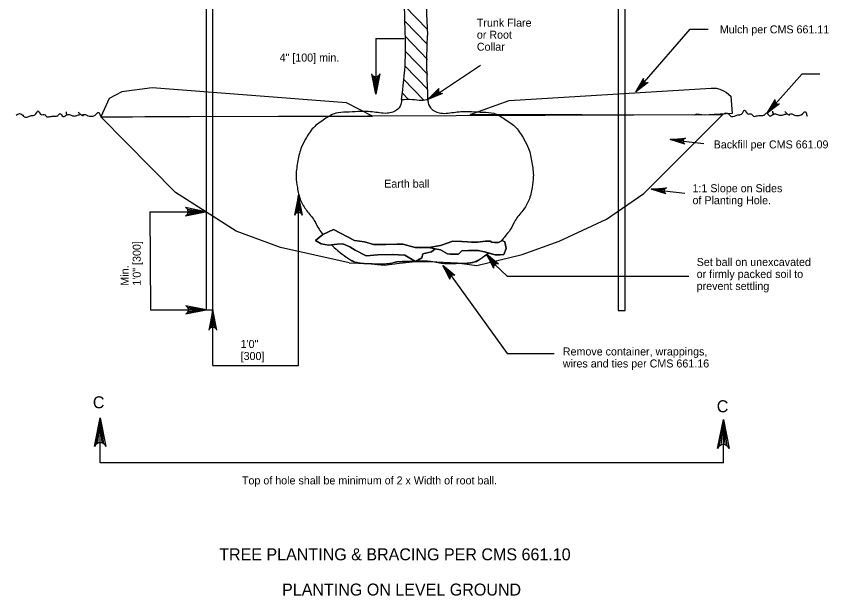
# Model space of a CAD drawing. Extents: x 3862.5 to 3891, y 3400.3 to 3419.7.
# Drawn here: x 3862.53 to 3876.75, y 3401.3 to 3411.44 of the extents above; entities that cross this region are included whole.
import ezdxf

# ---------------------------------------------------------------- set-up
doc = ezdxf.new("R2010")
doc.units = 0
doc.layers.add('DR_X_Trench_Drain', color=7, linetype='Continuous')
doc.layers.add('GT_X_Coal_Seam_1', color=7, linetype='Continuous')

msp = doc.modelspace()

# ---------------------------------------------------------------- linework, layer by layer
at = {"layer": 'DR_X_Trench_Drain'}
for p, q in [((3869.328, 3411.618), (3869.727, 3411.206)), ((3869.331, 3411.355), (3869.726, 3410.947)), ((3869.333, 3411.092), (3869.728, 3410.684)), ((3869.335, 3410.829), (3869.73, 3410.421)), ((3869.329, 3410.575), (3869.733, 3410.158)), ((3869.305, 3410.339), (3869.656, 3409.977)), ((3869.282, 3410.102), (3869.395, 3409.985)), ((3864.009, 3409.68), (3874.891, 3409.72)), ((3874.891, 3409.72), (3873.513, 3408.341)), ((3865.317, 3408.359), (3864.009, 3409.68))]:
    msp.add_line(p, q, dxfattribs=at)
for points in [[(3865.968, 3415.198), (3865.968, 3415.572), (3865.853, 3415.572), (3865.853, 3406.305), (3865.968, 3406.305), (3865.968, 3415.064)], [(3873.059, 3414.731), (3873.059, 3406.291), (3873.183, 3406.291), (3873.183, 3415.584), (3873.059, 3415.584), (3873.059, 3414.859)], [(3868.357, 3407.125), (3867.154, 3407.393), (3866.377, 3407.681), (3865.317, 3408.359)], [(3870.586, 3407.078), (3871.383, 3407.271), (3872.027, 3407.504), (3872.859, 3407.892), (3873.513, 3408.341)], [(3868.047, 3407.443), (3868.142, 3407.454), (3868.242, 3407.459), (3868.364, 3407.409), (3868.458, 3407.348), (3868.653, 3407.248), (3868.858, 3407.265), (3869.108, 3407.271), (3869.33, 3407.259), (3869.514, 3407.153), (3869.624, 3407.215), (3869.646, 3407.282), (3869.796, 3407.32), (3869.862, 3407.37), (3869.751, 3407.398), (3869.507, 3407.393), (3869.296, 3407.454), (3869.191, 3407.454), (3868.997, 3407.448), (3868.78, 3407.448), (3868.625, 3407.493), (3868.447, 3407.52), (3868.081, 3407.709), (3867.897, 3407.622), (3867.892, 3407.62), (3867.765, 3407.515), (3867.865, 3407.459), (3867.992, 3407.437), (3868.047, 3407.443)], [(3869.514, 3407.153), (3869.33, 3407.259), (3869.108, 3407.271), (3868.858, 3407.265), (3868.653, 3407.248), (3868.458, 3407.348), (3868.364, 3407.409), (3868.242, 3407.459), (3868.142, 3407.454), (3868.047, 3407.443)], [(3869.751, 3407.398), (3869.951, 3407.431), (3870.168, 3407.504), (3870.168, 3407.504), (3870.329, 3407.498), (3870.423, 3407.493), (3870.495, 3407.487), (3870.601, 3407.487), (3870.739, 3407.504), (3870.823, 3407.504), (3870.85, 3407.487), (3870.9, 3407.481), (3870.967, 3407.481), (3871.033, 3407.52), (3871.078, 3407.493), (3871.1, 3407.376), (3871.061, 3407.271), (3870.995, 3407.265), (3870.911, 3407.265), (3870.723, 3407.32), (3870.612, 3407.343), (3870.445, 3407.343), (3870.329, 3407.337), (3870.268, 3407.276), (3870.123, 3407.276), (3870.073, 3407.282), (3869.951, 3407.354), (3869.862, 3407.37)], [(3870.796, 3407.299), (3870.911, 3407.265), (3870.995, 3407.265), (3871.061, 3407.271), (3871.1, 3407.376), (3871.078, 3407.493), (3871.033, 3407.52), (3871.015, 3407.509), (3870.967, 3407.481), (3870.9, 3407.481), (3870.85, 3407.487), (3870.823, 3407.504), (3870.739, 3407.504), (3870.601, 3407.487), (3870.495, 3407.487), (3870.423, 3407.493), (3870.329, 3407.498), (3870.168, 3407.504), (3869.951, 3407.431), (3869.751, 3407.398), (3869.862, 3407.37), (3869.951, 3407.354), (3870.073, 3407.282), (3870.123, 3407.276), (3870.268, 3407.276), (3870.329, 3407.337), (3870.445, 3407.343), (3870.612, 3407.343), (3870.723, 3407.32), (3870.796, 3407.299)], [(3870.796, 3407.299), (3870.723, 3407.32), (3870.612, 3407.343), (3870.445, 3407.343), (3870.329, 3407.337), (3870.268, 3407.276), (3870.123, 3407.276), (3870.073, 3407.282), (3869.951, 3407.354), (3869.862, 3407.37), (3869.796, 3407.32), (3869.646, 3407.282), (3869.624, 3407.215), (3869.514, 3407.153)], [(3868.357, 3407.125), (3868.681, 3407.117), (3868.968, 3407.086), (3869.235, 3407.123), (3869.514, 3407.153), (3869.765, 3407.153), (3870.249, 3407.129), (3870.584, 3407.078), (3870.584, 3407.078), (3870.586, 3407.078)], [(3869.748, 3407.153), (3869.765, 3407.153), (3870.249, 3407.129), (3870.332, 3407.116)], [(3870.691, 3407.223), (3870.689, 3407.226), (3870.692, 3407.224)], [(3868.62, 3407.119), (3868.681, 3407.117), (3868.701, 3407.115)]]:
    msp.add_lwpolyline(points, dxfattribs=at)
for points in [[(3864.375, 3410.118), (3864.375, 3410.118), (3864.375, 3410.118), (3864.157, 3410.001), (3864.009, 3409.68), (3864.564, 3409.681), (3864.779, 3409.686), (3868.764, 3409.695), (3868.311, 3409.924), (3864.907, 3410.187)], [(3874.776, 3410.182), (3874.842, 3410.167), (3874.904, 3410.136), (3874.954, 3410.105), (3875.031, 3410.044), (3875.055, 3409.737), (3874.742, 3409.724), (3874.566, 3409.71), (3874.439, 3409.73), (3874.394, 3409.71), (3870.474, 3409.72), (3871.157, 3409.967), (3874.691, 3410.184)], [(3867.892, 3407.62), (3868.081, 3407.709), (3868.447, 3407.52), (3868.625, 3407.493), (3868.78, 3407.448), (3868.997, 3407.448), (3869.191, 3407.454), (3869.296, 3407.454), (3869.507, 3407.393), (3869.751, 3407.398), (3869.862, 3407.37), (3869.796, 3407.32), (3869.646, 3407.282), (3869.624, 3407.215), (3869.514, 3407.153), (3869.33, 3407.259), (3869.108, 3407.271), (3868.858, 3407.265), (3868.653, 3407.248), (3868.458, 3407.348), (3868.364, 3407.409), (3868.242, 3407.459), (3868.142, 3407.454), (3867.992, 3407.437), (3867.865, 3407.459), (3867.765, 3407.515)]]:
    msp.add_lwpolyline(points, close=True, dxfattribs=at)
for points in [[(3869.27, 3409.985), (3869.337, 3410.657), (3869.331, 3411.318), (3869.325, 3411.994), (3869.342, 3412.725), (3869.348, 3413.532), (3869.366, 3414.555), (3869.391, 3415.303), (3869.383, 3415.572)], [(3869.729, 3411.112), (3869.703, 3412.101), (3869.725, 3413.333), (3869.747, 3414.452), (3869.747, 3415.124), (3869.791, 3415.482)], [(3869.734, 3409.985), (3869.725, 3411.048), (3869.729, 3411.112)], [(3869.27, 3409.985), (3869.267, 3409.924), (3869.205, 3409.815), (3869.018, 3409.742), (3868.758, 3409.768), (3868.508, 3409.772), (3868.304, 3409.763), (3868.12, 3409.743), (3867.926, 3409.641), (3867.73, 3409.491), (3867.592, 3409.29), (3867.512, 3409.127), (3867.451, 3408.881), (3867.427, 3408.629), (3867.448, 3408.446), (3867.506, 3408.221), (3867.611, 3408.043), (3867.743, 3407.868), (3867.828, 3407.714), (3867.897, 3407.622)], [(3869.27, 3409.985), (3869.456, 3409.985), (3869.624, 3409.973), (3869.734, 3409.985)], [(3869.734, 3409.985), (3869.737, 3409.924), (3869.799, 3409.815), (3869.987, 3409.742), (3870.247, 3409.768), (3870.496, 3409.772), (3870.7, 3409.763), (3870.885, 3409.743), (3871.078, 3409.641), (3871.275, 3409.491), (3871.412, 3409.29), (3871.493, 3409.127), (3871.553, 3408.881), (3871.577, 3408.629), (3871.556, 3408.446), (3871.499, 3408.221), (3871.393, 3408.043), (3871.261, 3407.868), (3871.177, 3407.714), (3871.07, 3407.576), (3871.015, 3407.509)], [(3862.53, 3409.708), (3862.589, 3409.738), (3862.628, 3409.722), (3862.686, 3409.674), (3862.733, 3409.681), (3862.793, 3409.702), (3862.858, 3409.716), (3862.91, 3409.787), (3862.978, 3409.716), (3863.021, 3409.724), (3863.067, 3409.683), (3863.138, 3409.689), (3863.183, 3409.694), (3863.212, 3409.693), (3863.245, 3409.696), (3863.266, 3409.708), (3863.295, 3409.739), (3863.349, 3409.687), (3863.389, 3409.698), (3863.455, 3409.724), (3863.49, 3409.707), (3863.543, 3409.695), (3863.602, 3409.709), (3863.661, 3409.727)], [(3863.402, 3409.77), (3863.402, 3409.744), (3863.424, 3409.71)], [(3863.616, 3409.763), (3863.655, 3409.725), (3863.699, 3409.698)], [(3863.691, 3409.719), (3863.74, 3409.722), (3863.785, 3409.698), (3863.835, 3409.69), (3863.903, 3409.706), (3863.974, 3409.755), (3863.998, 3409.711), (3864.009, 3409.68)], [(3874.891, 3409.72), (3874.95, 3409.749), (3874.99, 3409.734), (3875.047, 3409.685), (3875.094, 3409.693), (3875.154, 3409.713), (3875.219, 3409.727), (3875.271, 3409.798), (3875.339, 3409.728), (3875.383, 3409.735), (3875.428, 3409.694), (3875.499, 3409.701), (3875.544, 3409.705), (3875.573, 3409.704), (3875.606, 3409.707), (3875.628, 3409.719), (3875.656, 3409.75), (3875.711, 3409.698), (3875.75, 3409.709), (3875.817, 3409.736), (3875.851, 3409.719), (3875.904, 3409.707), (3875.963, 3409.721), (3876.022, 3409.738)], [(3875.764, 3409.781), (3875.764, 3409.755), (3875.785, 3409.722)], [(3875.977, 3409.775), (3876.016, 3409.736), (3876.06, 3409.709)], [(3876.052, 3409.73), (3876.101, 3409.734), (3876.146, 3409.709), (3876.196, 3409.702), (3876.264, 3409.717), (3876.335, 3409.767), (3876.359, 3409.722), (3876.37, 3409.692)], [(3868.047, 3407.443), (3868.062, 3407.427), (3868.193, 3407.311), (3868.348, 3407.199), (3868.467, 3407.14), (3868.701, 3407.115), (3869.013, 3407.113), (3869.247, 3407.152), (3869.514, 3407.153)], [(3870.796, 3407.299), (3870.657, 3407.199), (3870.537, 3407.14), (3870.303, 3407.115), (3869.992, 3407.113), (3869.757, 3407.152), (3869.514, 3407.153)]]:
    msp.add_spline(points, degree=3, dxfattribs=at)
for points, degree in [([(3868.047, 3407.443), (3868.052, 3407.438), (3868.057, 3407.433), (3868.062, 3407.427), (3868.102, 3407.384), (3868.148, 3407.348), (3868.193, 3407.311), (3868.243, 3407.271), (3868.294, 3407.235), (3868.348, 3407.199), (3868.385, 3407.175), (3868.423, 3407.151), (3868.467, 3407.14), (3868.518, 3407.127), (3868.569, 3407.122), (3868.62, 3407.119)], 3), ([(3870.692, 3407.224), (3870.728, 3407.248), (3870.762, 3407.273), (3870.796, 3407.299)], 2), ([(3868.701, 3407.115), (3868.701, 3407.115), (3868.701, 3407.115), (3868.701, 3407.115), (3868.805, 3407.111), (3868.91, 3407.107), (3869.013, 3407.113), (3869.092, 3407.118), (3869.168, 3407.152), (3869.247, 3407.152), (3869.336, 3407.153), (3869.425, 3407.153), (3869.514, 3407.153)], 3), ([(3869.514, 3407.153), (3869.592, 3407.158), (3869.671, 3407.158), (3869.748, 3407.153)], 2), ([(3870.332, 3407.116), (3870.401, 3407.119), (3870.469, 3407.123), (3870.537, 3407.14), (3870.581, 3407.151), (3870.62, 3407.174), (3870.657, 3407.199), (3870.668, 3407.207), (3870.68, 3407.215), (3870.691, 3407.223)], 3)]:
    msp.add_open_spline(points, degree=degree, dxfattribs=at)
at = {"layer": 'GT_X_Coal_Seam_1'}
for p, q in [((3873.521, 3410.29), (3874.324, 3411.213)), ((3874.324, 3411.213), (3874.636, 3411.213)), ((3868.819, 3411.051), (3868.819, 3410.077)), ((3868.819, 3411.051), (3869.319, 3411.051)), ((3869.919, 3410.096), (3870.653, 3410.586)), ((3868.775, 3410.397), (3868.819, 3410.077)), ((3868.869, 3410.401), (3868.819, 3410.077)), ((3875.671, 3409.745), (3876.279, 3410.434)), ((3876.279, 3410.434), (3876.591, 3410.434)), ((3868.797, 3410.386), (3868.819, 3410.077)), ((3868.848, 3410.389), (3868.819, 3410.077)), ((3868.819, 3410.383), (3868.819, 3410.077)), ((3873.503, 3410.32), (3873.369, 3410.117)), ((3873.51, 3410.303), (3873.369, 3410.117)), ((3873.521, 3410.29), (3873.369, 3410.117)), ((3873.54, 3410.279), (3873.369, 3410.117)), ((3873.558, 3410.275), (3873.369, 3410.117)), ((3869.916, 3410.147), (3869.734, 3409.985)), ((3869.918, 3410.129), (3869.734, 3409.985)), ((3869.926, 3410.113), (3869.734, 3409.985)), ((3869.941, 3410.097), (3869.734, 3409.985)), ((3869.958, 3410.089), (3869.734, 3409.985)), ((3875.805, 3409.948), (3875.671, 3409.745)), ((3875.812, 3409.931), (3875.671, 3409.745)), ((3875.823, 3409.918), (3875.671, 3409.745)), ((3875.842, 3409.907), (3875.671, 3409.745)), ((3875.86, 3409.903), (3875.671, 3409.745)), ((3874.213, 3409.292), (3873.97, 3409.285)), ((3874.198, 3409.259), (3873.97, 3409.285)), ((3874.2, 3409.237), (3873.97, 3409.285)), ((3874.208, 3409.221), (3873.97, 3409.285)), ((3874.203, 3409.276), (3873.97, 3409.285)), ((3874.207, 3409.254), (3874.56, 3409.212)), ((3873.88, 3408.423), (3873.637, 3408.416)), ((3873.866, 3408.391), (3873.637, 3408.416)), ((3873.868, 3408.369), (3873.637, 3408.416)), ((3873.875, 3408.352), (3873.637, 3408.416)), ((3873.87, 3408.407), (3873.637, 3408.416)), ((3867.423, 3407.992), (3867.468, 3408.313)), ((3867.445, 3408.003), (3867.468, 3408.313)), ((3867.468, 3408.006), (3867.468, 3408.313)), ((3867.497, 3408.001), (3867.468, 3408.313)), ((3867.518, 3407.988), (3867.468, 3408.313)), ((3873.875, 3408.385), (3874.227, 3408.343)), ((3864.87, 3408.022), (3865.844, 3408.022)), ((3864.87, 3408.022), (3864.879, 3406.305)), ((3865.52, 3407.972), (3865.844, 3408.022)), ((3865.524, 3408.067), (3865.844, 3408.022)), ((3865.532, 3407.993), (3865.844, 3408.022)), ((3865.534, 3408.044), (3865.844, 3408.022)), ((3865.538, 3408.022), (3865.844, 3408.022)), ((3867.468, 3405.33), (3867.468, 3408.006)), ((3870.901, 3407.097), (3870.758, 3407.277)), ((3870.921, 3407.107), (3870.758, 3407.277)), ((3870.939, 3407.109), (3870.758, 3407.277)), ((3870.889, 3407.084), (3870.758, 3407.277)), ((3870.881, 3407.067), (3870.758, 3407.277)), ((3870.139, 3406.901), (3869.996, 3407.082)), ((3870.158, 3406.911), (3869.996, 3407.082)), ((3870.176, 3406.914), (3869.996, 3407.082)), ((3870.127, 3406.889), (3869.996, 3407.082)), ((3870.119, 3406.872), (3869.996, 3407.082)), ((3871.117, 3406.894), (3870.901, 3407.097)), ((3870.139, 3406.901), (3871.117, 3405.539)), ((3871.117, 3406.894), (3874.296, 3406.894)), ((3864.879, 3406.305), (3865.853, 3406.305)), ((3865.528, 3406.255), (3865.853, 3406.305)), ((3865.532, 3406.349), (3865.853, 3406.305)), ((3865.541, 3406.276), (3865.853, 3406.305)), ((3865.543, 3406.327), (3865.853, 3406.305)), ((3865.546, 3406.305), (3865.853, 3406.305)), ((3865.923, 3405.984), (3865.968, 3406.305)), ((3865.945, 3405.995), (3865.968, 3406.305)), ((3865.968, 3405.33), (3865.968, 3406.305)), ((3865.968, 3405.998), (3865.968, 3406.305)), ((3865.997, 3405.992), (3865.968, 3406.305)), ((3866.018, 3405.98), (3865.968, 3406.305)), ((3871.117, 3405.539), (3871.94, 3405.539)), ((3865.968, 3405.33), (3867.468, 3405.33)), ((3863.929, 3403.956), (3863.999, 3404.418)), ((3863.958, 3403.973), (3863.999, 3404.418)), ((3863.999, 3403.632), (3863.999, 3404.418)), ((3863.999, 3403.982), (3863.999, 3404.418)), ((3864.032, 3403.977), (3863.999, 3404.418)), ((3864.063, 3403.961), (3863.999, 3404.418)), ((3863.999, 3403.632), (3863.999, 3404.327)), ((3874.831, 3403.922), (3874.902, 3404.385)), ((3874.861, 3403.94), (3874.902, 3404.385)), ((3874.902, 3403.632), (3874.902, 3404.385)), ((3874.902, 3403.948), (3874.902, 3404.385)), ((3874.934, 3403.943), (3874.902, 3404.385)), ((3874.966, 3403.928), (3874.902, 3404.385)), ((3874.902, 3403.632), (3863.999, 3403.632))]:
    msp.add_line(p, q, dxfattribs=at)
for points in [[(3868.89, 3410.431), (3868.819, 3410.077), (3868.749, 3410.431)], [(3873.585, 3410.281), (3873.369, 3410.117), (3873.505, 3410.352)], [(3869.985, 3410.089), (3869.734, 3409.985), (3869.926, 3410.177)], [(3875.887, 3409.91), (3875.671, 3409.745), (3875.807, 3409.98)], [(3874.228, 3409.203), (3873.97, 3409.285), (3874.24, 3409.308)], [(3873.896, 3408.334), (3873.637, 3408.416), (3873.908, 3408.44)], [(3867.539, 3407.959), (3867.468, 3408.313), (3867.397, 3407.959)], [(3865.49, 3407.951), (3865.844, 3408.022), (3865.49, 3408.093)], [(3870.965, 3407.102), (3870.758, 3407.277), (3870.882, 3407.036)], [(3870.203, 3406.906), (3869.996, 3407.082), (3870.119, 3406.84)], [(3865.499, 3406.234), (3865.853, 3406.305), (3865.499, 3406.375)], [(3866.039, 3405.95), (3865.968, 3406.305), (3865.897, 3405.95)], [(3863.898, 3403.913), (3863.999, 3404.418), (3864.1, 3403.913)], [(3874.801, 3403.88), (3874.902, 3404.385), (3875.003, 3403.88)]]:
    msp.add_lwpolyline(points, dxfattribs=at)
for centre, radius, start, end in [((3868.819, 3410.459), 0.0764, 202.0878, 337.9139), ((3873.559, 3410.333), 0.0574, 160.6589, 296.485), ((3869.973, 3410.145), 0.0574, 145.7478, 281.574), ((3875.861, 3409.961), 0.0574, 160.6589, 296.485), ((3874.255, 3409.253), 0.0574, 105.7478, 241.574), ((3873.923, 3408.384), 0.0574, 105.7478, 241.574), ((3865.461, 3408.022), 0.0764, 292.0861, 67.9122), ((3867.468, 3407.93), 0.0764, 22.0861, 157.9122), ((3870.937, 3407.052), 0.0574, 60.4695, 196.2956), ((3870.174, 3406.856), 0.0574, 60.4695, 196.2956), ((3865.47, 3406.305), 0.0764, 292.0861, 67.9122), ((3865.968, 3405.922), 0.0764, 22.0861, 157.9122), ((3864, 3403.873), 0.109, 22.0878, 157.9139), ((3874.902, 3403.839), 0.109, 22.0878, 157.9139)]:
    msp.add_arc(centre, radius, start, end, dxfattribs=at)

# ---------------------------------------------------------------- texts
for s, height, p in [('Trunk Flare', 0.14, (3870.589, 3411.257)), ('Mulch per CMS 661.11', 0.14, (3874.84, 3411.14)), ('or Root', 0.14, (3870.589, 3411.047)), ('Collar', 0.14, (3870.589, 3410.837)), ('4" [100] min.', 0.14, (3867.138, 3410.647)), ('Backfill per CMS 661.09', 0.14, (3874.732, 3409.128)), ('Earth ball', 0.14, (3868.968, 3408.442)), ('1:1 Slope on Sides', 0.14, (3874.362, 3408.362)), ('of Planting Hole.', 0.14, (3874.362, 3408.152)), ('Set ball on unexcavated', 0.14, (3874.435, 3407.072)), ('or firmly packed soil to', 0.14, (3874.435, 3406.862)), ('prevent settling', 0.14, (3874.435, 3406.652)), ('1\'0"', 0.14, (3866.456, 3405.638)), ('[300]', 0.14, (3866.456, 3405.428)), ('Remove container, wrappings,', 0.14, (3872.093, 3405.507)), ('wires and ties per CMS 661.16', 0.14, (3872.093, 3405.297)), ('C', 0.21, (3863.87, 3404.583)), ('C', 0.21, (3874.786, 3404.514)), ('Top of hole shall be minimum of 2 x Width of root ball.', 0.14, (3866.479, 3403.252)), ('TREE PLANTING & BRACING PER CMS 661.10', 0.21, (3866.081, 3401.924)), ('PLANTING ON LEVEL GROUND ', 0.21, (3867.181, 3401.308))]:
    msp.add_text(s, height=height, dxfattribs=at).set_placement(p)
for s, p in [('1\'0" [300]', (3864.708, 3406.728)), ('Min.', (3864.498, 3406.728))]:
    msp.add_text(s, height=0.14, rotation=90, dxfattribs=at).set_placement(p)

doc.saveas('drawing.dxf')
